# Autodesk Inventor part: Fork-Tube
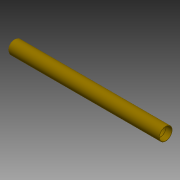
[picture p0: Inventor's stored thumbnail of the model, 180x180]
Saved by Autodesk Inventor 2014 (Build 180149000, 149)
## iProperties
Shininess: 64.0
Length Units: 11272
Angle Units: 11279
Time Units: 11290
Mass Units: 11286
Length Display Precision: 3
Angle Display Precision: 2
Compacted: True
Created: 2001-11
Part Number: Fork-Tube
Document SubType Name: Modeling
Designer: Autodesk, Inc.
Mass: 63.0746 g
Surface Area: 510.582 cm^2
Volume: 63.0746 cm^3
Density: 1 g/cm^3
Material: Generic
Appearance: Gold
Density: 0.0
Volumn: 0.0
Area: 0.0
PropertySet Name: Model Information
Control State: 0
Master: False
Checked Out: False
Author: Autodesk, Inc.
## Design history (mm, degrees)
sketch "Sketch1"
  geometry: L1 (361.822, 239.265)-(361.822, 240.154); L2 (361.822, 240.154)-(364.362, 241.805); L3 (364.362, 241.805)-(679.322, 241.805); L4 (679.322, 240.535)-(679.322, 241.805); L5 (667.892, 240.535)-(679.322, 240.535); L6 (667.892, 239.265)-(667.892, 240.535); L7 (361.822, 239.265)-(667.892, 239.265); L8 (345.987, 227.835)-(749.871, 227.835); L9 (345.987, 227.835)-(749.871, 227.835)
  constraints: 18 end point, 4 horizontal, 3 vertical, 1 other
revolve "RevolutionFull1" sketch "Sketch1" stored, may be unused: angle "d0" = 360 deg
body "Solid1"
